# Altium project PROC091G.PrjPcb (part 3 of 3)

## Sheet PROC091G_CAN_INTERFACE.SchDoc: BREAKAWAY_SECTION5
size 431 x 279 mm; Date: Not shown in title block; ApprovedBy: Not shown in title block; CheckedBy: Not shown in title block; Author: Not shown in title block; CompanyName: Not shown in title block; DrawnBy: Antony/Bala; Engineer: Not shown in title block; Organization: Not shown in title block; Address1: Not shown in title block; Address2: Not shown in title block; Address3: Not shown in title block; Address4: Not shown in title block; DocumentNumber: 11; Revision: Use project parameter SCH_Rev; SheetNumber: 11; SheetTotal: 12; PageSetup: Record=PageOptions¦CenterHorizontal=True¦CenterVertical=True¦PrintScale=1.00¦XCorrection=1.00¦YCorrection=1.00¦PrintKind=0¦BorderSize=5000000¦LeftOffset=0¦BottomOffset=0¦Orientation=2¦PaperLength=1000¦PaperWidth=1000¦Scale=100¦PaperSource=15¦PrintQuality=600¦MediaType=1¦DitherType=10¦PaperKind=Letter¦PrintScaleMode=1
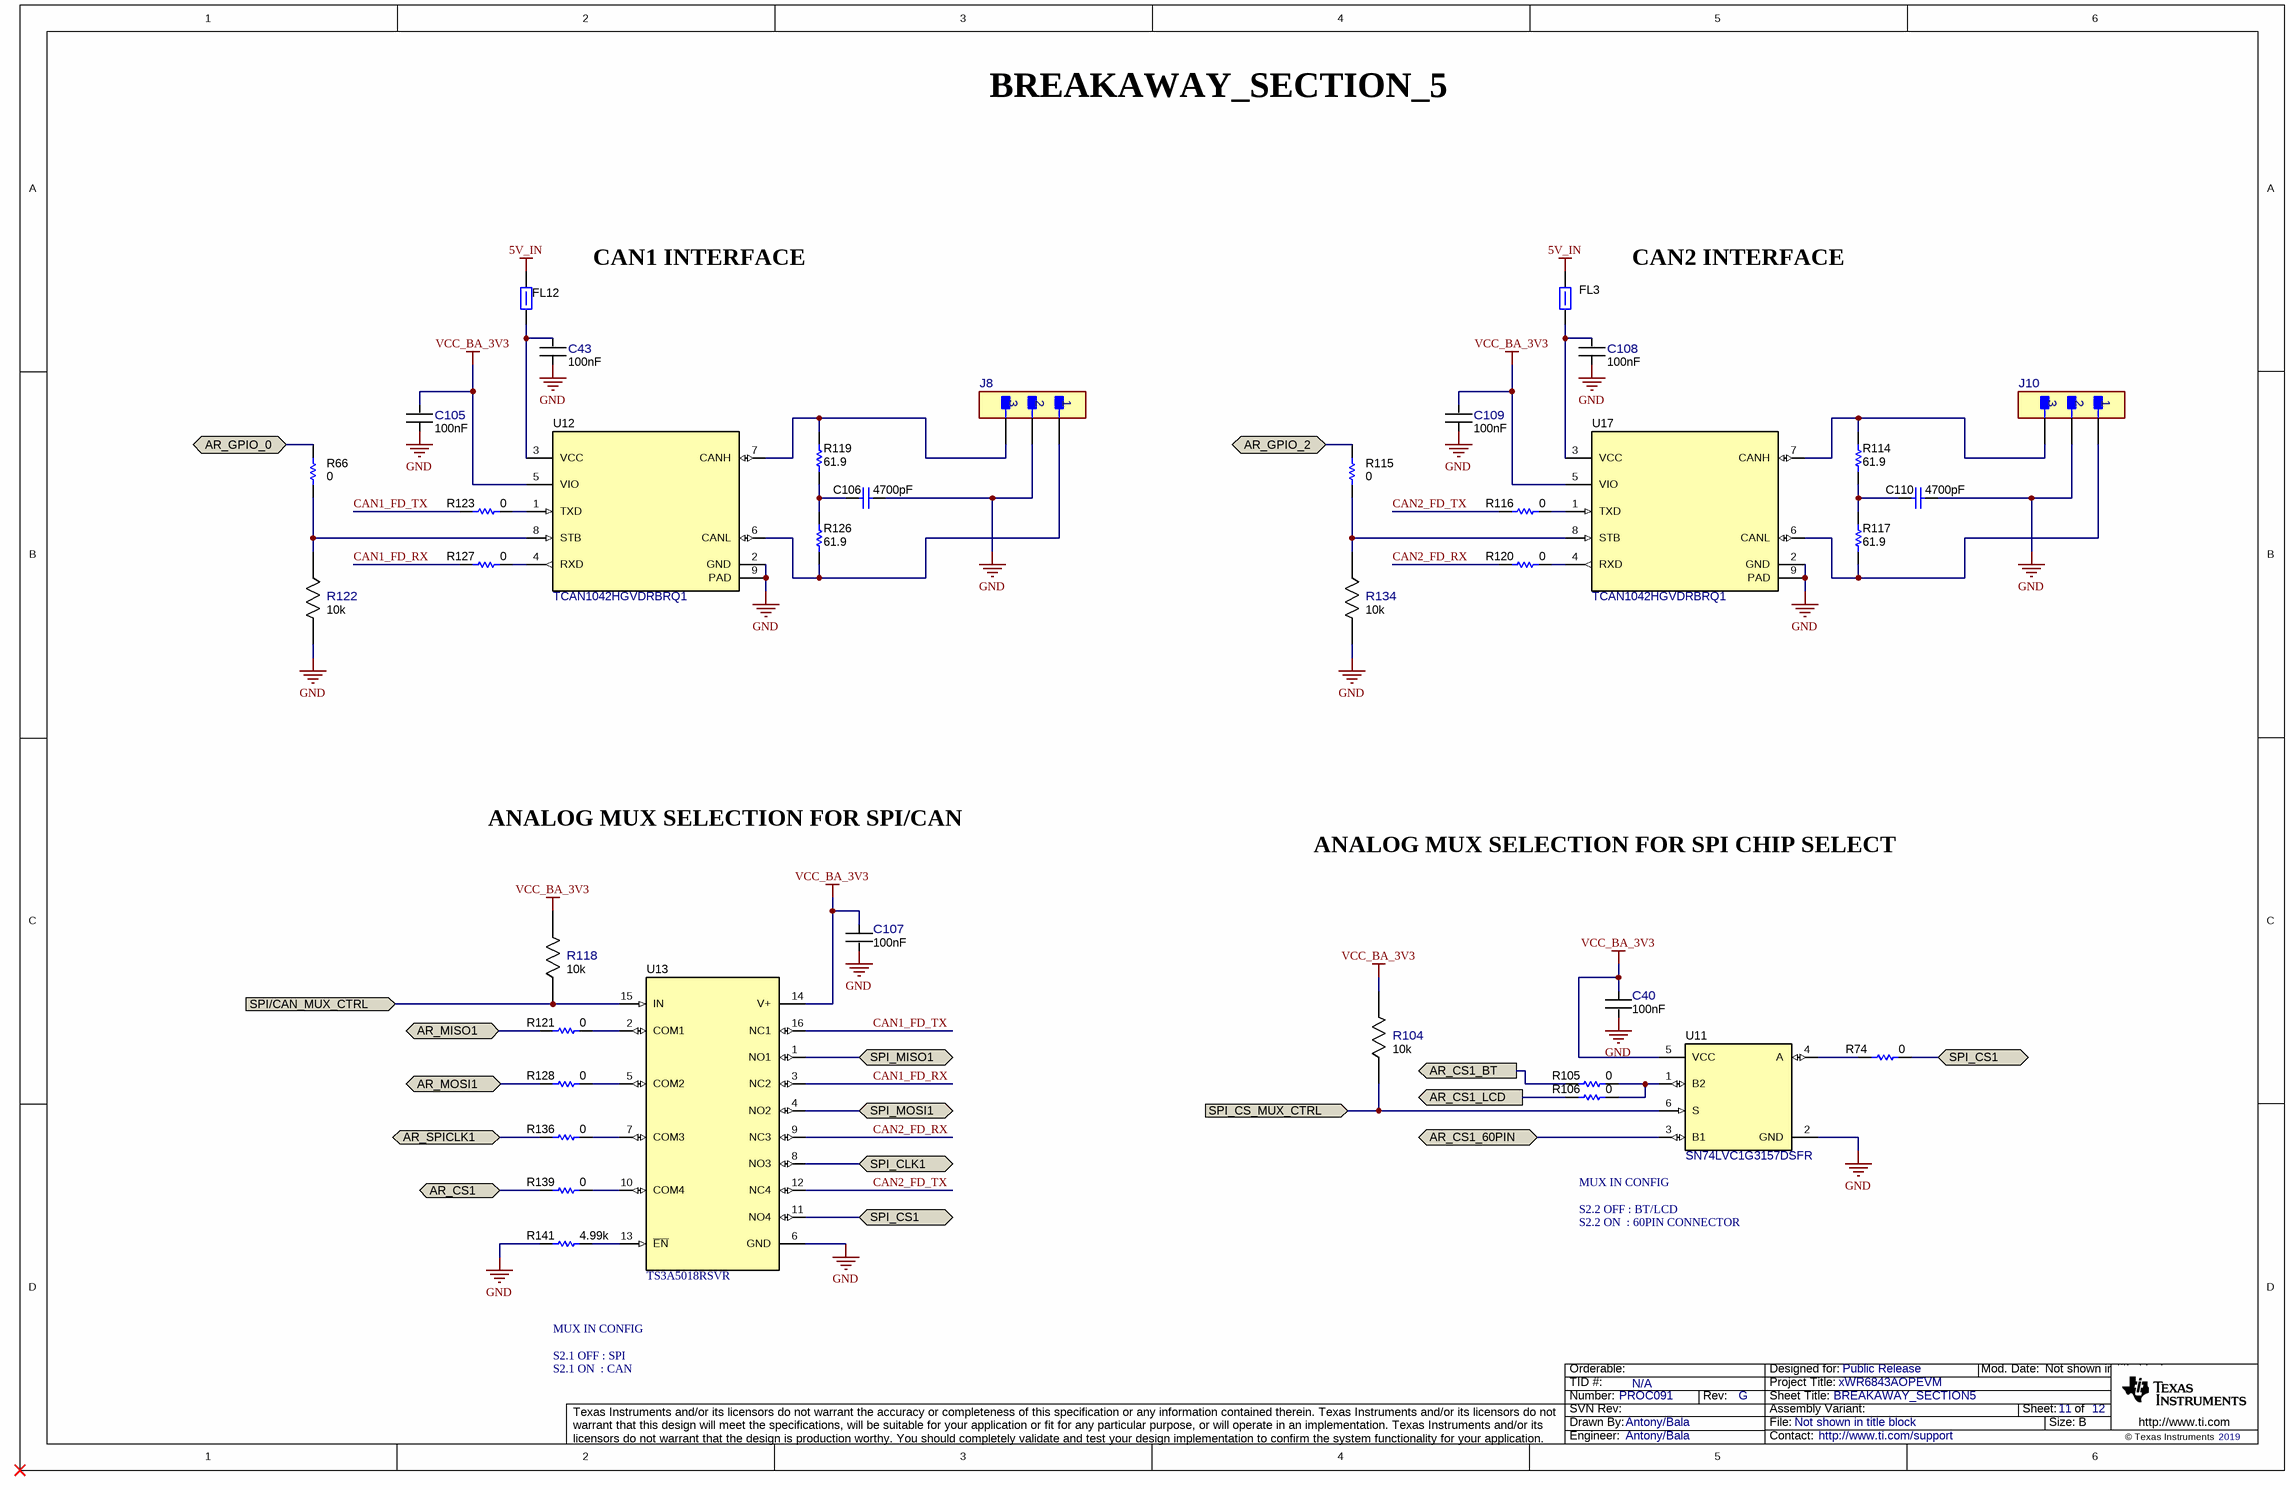
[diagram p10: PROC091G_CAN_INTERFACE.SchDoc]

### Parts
C40  Cap_F: 100nF  [FP-GRM033R6YA104KE14D_0201 (0603 Metric)-IPC_C]  (hidden comment: GRM033R6YA104KE14D)
C43  Cap_F: 100nF  [FP-GRM033R6YA104KE14D_0201 (0603 Metric)-IPC_C]  (hidden comment: GRM033R6YA104KE14D)
C105  Cap_F: 100nF  [FP-GRM033R6YA104KE14D_0201 (0603 Metric)-IPC_C]  (hidden comment: GRM033R6YA104KE14D)
C106  ValueDisplayed: 4700pF  [0402L]  (hidden comment: GRM155R71H472KA01D)
C107  Cap_F: 100nF  [FP-GRM033R6YA104KE14D_0201 (0603 Metric)-IPC_C]  (hidden comment: GRM033R6YA104KE14D)
C108  Cap_F: 100nF  [FP-GRM033R6YA104KE14D_0201 (0603 Metric)-IPC_C]  (hidden comment: GRM033R6YA104KE14D)
C109  Cap_F: 100nF  [FP-GRM033R6YA104KE14D_0201 (0603 Metric)-IPC_C]  (hidden comment: GRM033R6YA104KE14D)
C110  ValueDisplayed: 4700pF  [0402L]  (hidden comment: GRM155R71H472KA01D)
FL3  BLM15PD300SZ1D  [0402L]  (value not drawn)
FL12  BLM15PD300SZ1D  [0402L]  (value not drawn)
J8  M50-3930342  [FP-M50-3930342_HDR3-MFG]  (value not drawn)
J10  M50-3930342  [FP-M50-3930342_HDR3-MFG]  (value not drawn)
R66  Res_ohm: 0  [FP-RC0201JR-070RL_0201 (0603 Metric)-IPC_C]  (hidden comment: RC0201JR-070RL)
R74  Res_ohm: 0  [FP-RC0201JR-070RL_0201 (0603 Metric)-IPC_C]  (hidden comment: RC0201JR-070RL)
R104  Res_ohm: 10k  [FP-RR0306P-103-D_0201-IPC_C]  (hidden comment: RR0306P-103-D)
R105  Res_ohm: 0  [FP-RC0201JR-070RL_0201 (0603 Metric)-IPC_C]  (hidden comment: RC0201JR-070RL)
R106  Res_ohm: 0  [FP-RC0201JR-070RL_0201 (0603 Metric)-IPC_C]  (hidden comment: RC0201JR-070RL)
R114  ValueDisplayed: 61.9  [0402L]  (hidden comment: CRCW040261R9FKED)
R115  Res_ohm: 0  [FP-RC0201JR-070RL_0201 (0603 Metric)-IPC_C]  (hidden comment: RC0201JR-070RL)
R116  Res_ohm: 0  [FP-RC0201JR-070RL_0201 (0603 Metric)-IPC_C]  (hidden comment: RC0201JR-070RL)
R117  ValueDisplayed: 61.9  [0402L]  (hidden comment: CRCW040261R9FKED)
R118  Res_ohm: 10k  [FP-RR0306P-103-D_0201-IPC_C]  (hidden comment: RR0306P-103-D)
R119  ValueDisplayed: 61.9  [0402L]  (hidden comment: CRCW040261R9FKED)
R120  Res_ohm: 0  [FP-RC0201JR-070RL_0201 (0603 Metric)-IPC_C]  (hidden comment: RC0201JR-070RL)
R121  Res_ohm: 0  [FP-RC0201JR-070RL_0201 (0603 Metric)-IPC_C]  (hidden comment: RC0201JR-070RL)
R122  Res_ohm: 10k  [FP-RR0306P-103-D_0201-IPC_C]  (hidden comment: RR0306P-103-D)
R123  Res_ohm: 0  [FP-RC0201JR-070RL_0201 (0603 Metric)-IPC_C]  (hidden comment: RC0201JR-070RL)
R126  ValueDisplayed: 61.9  [0402L]  (hidden comment: CRCW040261R9FKED)
R127  Res_ohm: 0  [FP-RC0201JR-070RL_0201 (0603 Metric)-IPC_C]  (hidden comment: RC0201JR-070RL)
R128  Res_ohm: 0  [FP-RC0201JR-070RL_0201 (0603 Metric)-IPC_C]  (hidden comment: RC0201JR-070RL)
R134  Res_ohm: 10k  [FP-RR0306P-103-D_0201-IPC_C]  (hidden comment: RR0306P-103-D)
R136  Res_ohm: 0  [FP-RC0201JR-070RL_0201 (0603 Metric)-IPC_C]  (hidden comment: RC0201JR-070RL)
R139  Res_ohm: 0  [FP-RC0201JR-070RL_0201 (0603 Metric)-IPC_C]  (hidden comment: RC0201JR-070RL)
R141  value 4.99k  [0201L]  (hidden comment: RC0201FR-074K99L)
U11  SN74LVC1G3157DSFR  [DSF0006A]
U12  TCAN1042HGVDRBRQ1  [DRB0008F]
U13  TS3A5018RSVR  [RSV0016A]
U17  TCAN1042HGVDRBRQ1  [DRB0008F]

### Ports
AR_CS1 (bidir), AR_CS1_60PIN (bidir), AR_CS1_BT (out), AR_CS1_LCD (out), AR_GPIO_0 (bidir), AR_GPIO_2 (bidir), AR_MISO1 (bidir), AR_MOSI1 (bidir), AR_SPICLK1 (bidir), SPI/CAN_MUX_CTRL (in), SPI_CLK1 (bidir), SPI_CS1 (bidir), SPI_CS_MUX_CTRL (in), SPI_MISO1 (bidir), SPI_MOSI1 (bidir)

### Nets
5V_IN: FL3.2 FL12.2
GND: C40.2 C43.1 C105.1 C106.1 C107.2 C108.1 C109.1 C110.1 J8.2 J10.2 R122.2 R134.2 R141.2 U11.2(GND) U12.2(GND) U12.9(PAD) U13.6(GND) U17.2(GND) U17.9(PAD)
VCC_BA_3V3: C40.1 C105.2 C107.1 C109.2 R104.2 R118.2 U11.5(VCC) U12.5(VIO) U13.14(V+) U17.5(VIO)
AR_CS1: R139.2 ; port AR_CS1
AR_CS1_60PIN: U11.3(B1) ; port AR_CS1_60PIN
AR_CS1_BT: R105.2 ; port AR_CS1_BT
AR_CS1_LCD: R106.2 ; port AR_CS1_LCD
AR_GPIO_0: R66.1 ; port AR_GPIO_0
AR_GPIO_2: R115.1 ; port AR_GPIO_2
AR_MISO1: R121.2 ; port AR_MISO1
AR_MOSI1: R128.2 ; port AR_MOSI1
AR_SPICLK1: R136.2 ; port AR_SPICLK1
CAN1_FD_RX: R127.2 U13.3(NC2)
CAN1_FD_TX: R123.2 U13.16(NC1)
CAN2_FD_RX: R120.2 U13.9(NC3)
CAN2_FD_TX: R116.2 U13.12(NC4)
SPI/CAN_MUX_CTRL: R118.1 U13.15(IN) ; port SPI/CAN_MUX_CTRL
SPI_CLK1: U13.8(NO3) ; port SPI_CLK1
SPI_CS1: R74.1 U13.11(NO4) ; port SPI_CS1
SPI_CS_MUX_CTRL: R104.1 U11.6(S) ; port SPI_CS_MUX_CTRL
SPI_MISO1: U13.1(NO1) ; port SPI_MISO1
SPI_MOSI1: U13.4(NO2) ; port SPI_MOSI1
NetC43_2: C43.2 FL12.1 U12.3(VCC)
NetC106_2: C106.2 R119.1 R126.2
NetC108_2: C108.2 FL3.1 U17.3(VCC)
NetC110_2: C110.2 R114.1 R117.2
NetJ8_1: J8.1 R126.1 U12.6(CANL)
NetJ8_3: J8.3 R119.2 U12.7(CANH)
NetJ10_1: J10.1 R117.1 U17.6(CANL)
NetJ10_3: J10.3 R114.2 U17.7(CANH)
NetR66_2: R66.2 R122.1 U12.8(STB)
NetR74_2: R74.2 U11.4(A)
NetR105_1: R105.1 R106.1 U11.1(B2)
NetR115_2: R115.2 R134.1 U17.8(STB)
NetR116_1: R116.1 U17.1(TXD)
NetR120_1: R120.1 U17.4(RXD)
NetR121_1: R121.1 U13.2(COM1)
NetR123_1: R123.1 U12.1(TXD)
NetR127_1: R127.1 U12.4(RXD)
NetR128_1: R128.1 U13.5(COM2)
NetR136_1: R136.1 U13.7(COM3)
NetR139_1: R139.1 U13.10(COM4)
NetR141_1: R141.1 U13.13(~{EN})

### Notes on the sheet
- BREAKAWAY_SECTION_5
- CAN1 INTERFACE
- CAN2 INTERFACE
- ANALOG MUX SELECTION FOR SPI/CAN
- ANALOG MUX SELECTION FOR SPI CHIP SELECT
- (near U11) MUX IN CONFIG
- S2.2 ON  : 60PIN CONNECTOR
- S2.2 OFF : BT/LCD
- MUX IN CONFIG
- S2.1 OFF : SPI
- S2.1 ON  : CAN

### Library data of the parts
C40 C43 C105 C107-C109 = CMP-0086440-1: Cap Ceramic 0.1uF 35V X5R 10% Pad SMD 0201 85C T/R; Manufacturer: Murata Electronics North America; AEC Qualified: No; SizeZ_mm: 0.33mm; Symbol Name: SYM-GRM033R6YA104KE14D; TempCo: 15%
C106 C110 = CMP-0006692-2: CAP, CERM, 4700 pF, 50 V, +/- 10%, X7R, 0402; Manufacturer: MuRata; TaMin_C: -55°C; Polarized: N; SizeAreaWB_mm2: 3; Value1: Unknown; U/M: EA; Value: 4700pF; TaMax_C: 125°C; SizeZ_mm: 0.6; SizeX_mm: 1; SizeY_mm: 0.5; Cap_Case: 0402; Value2: 50V; Cap_F: 4.7nF; AEC Category: Q200
FL3 FL12 = CMP-0078934-1: Inductor, Ferrite Bead, Ferrite, 2.2 A, 0.035 ohm, AEC-Q200 Grade 1, SMD; Manufacturer: MuRata; AEC Category: Q200; AEC Grade: 1; AEC Qualified: Y; DCR_ohm: 0.035; Imax_A: 2.2A; SizeArea_mm2: 0.5; SizeAreaWB_mm2: 3; SizeZ_mm: 0.6
J8 J10 = CMP-0087785-1: CONN HEADER R/A 3POS 1.27MM; Manufacturer: Harwin; Row_Count: 1; Current_A: 1A; ContactFinish: Gold,Nickel
R66 R74 R105 R106 R115 R116 R120 R121 R123 R127 R128 R136 R139 = CMP-0086442-2: RES SMD 0 OHM JUMPER 1/20W 0201; Manufacturer: Yageo; AEC Qualified: No; Power_W: 50mW; SizeZ_mm: 0.26mm; TempCo: 200ppm/°C; Tolerance_%: 5%; VDC_V: 25V
R104 R118 R122 R134 = CMP-0088002-1: 10 kOhms ±0.5% 0.05W, 1/20W Chip Resistor 0201 (0603 Metric)  Thin Film; Manufacturer: Susumu; AEC Qualified: No; Power_W: 50mW; SizeZ_mm: 0.26mm; Symbol Name: SYM-RR0306P-103-D; TempCo: 25ppm/°C; VDC_V: 15V
R114 R117 R119 R126 = CMP-0026491-2: RES, 61.9, 1%, 0.063 W, AEC-Q200 Grade 0, 0402; Manufacturer: Vishay-Dale; Power_W: 63mW; TempCo: 100 ppm/C; Value_Code: 61R9; Value: 61.9; EIA_Code: E96; SizeX_mm: 1; SizeY_mm: 0.5; SizeZ_mm: 0.6; Value2: 0.063W; AEC Qualified: Y; VDC_V: 50V; AEC Category: Q200; AEC Grade: 0
R141 = CMP-0027745-1: RES, 4.99 k, 1%, 0.05 W, 0201; Manufacturer: Yageo America; AEC Category: Q200; AEC Qualified: N; EIA_Code: E96; Power_W: 50mW; SizeArea_mm2: 0.18; SizeX_mm: 0.6; SizeY_mm: 0.3; SizeZ_mm: 0.26; TempCo: 200 ppm/C; U/M: EA; Value2: 0.05W; Value_Code: 4k99; VDC_V: 25V
U11 = CMP-0050992-5: 1-Channel, 2:1 Analog Switch, DSF0006A (X2SON-6); Manufacturer: Texas Instruments; 3-State Output: No; AEC Category: Q200; AEC Qualified: N; Bits(#): 1; CompType: IC; F @ Nom Voltage(Max)(Mhz): 150; ICC @ Nom Voltage(Max)(mA): 0.01; Input Type: CMOS/TTL; Logic: True; Mux Configuration: 1：2; Output Drive (IOL/IOH)(Max)(mA): 32/-32; Output Type: CMOS; Rating: Catalog; Switch Configuration: SPDT; Technology Family: LVC; tpd @ Nom Voltage(Max)(ns): 2,1.2,0.8,0.3; VCC(Max)(V): 5.5; VCC(Min)(V): 1.65; Voltage(Nom)(V): 1.8,2.5,3.3,5
U12 U17 = CMP-0065183-3: Automotive Fault Protected CAN Transceiver With Flexible Data-Rate, DRB0008F (VSON-8); Manufacturer: Texas Instruments; Alternate PartNumber: TCAN1042HGVDRBTQ1; SizeX_mm: 3.0; CompType: IC; SizeZ_mm: 1.0; SizeArea_mm2: 9.0; SizeAreaWB_mm2: 16.0; AEC Category: Q200; AEC Qualified: Y
U13 = CMP-0067415-1: 10-Ohm Quad SPDT Analog Switch, RSV0016A (UQFN-16); Alternate Manufacturer: Texas Instruments; SizeAreaWB_mm2: 10.08; U/M: EA; SizeZ_mm: 0.55; SizeX_mm: 1.8; SizeY_mm: 2.6; SizeArea_mm2: 4.68; CompType: IC

## Sheet PROC091G_Hardware.schdoc: HARDWARE
size 431 x 279 mm; Date: Not shown in title block; ApprovedBy: Not shown in title block; CheckedBy: Not shown in title block; Author: Not shown in title block; CompanyName: Not shown in title block; DrawnBy: Antony/Bala; Engineer: Not shown in title block; Organization: Not shown in title block; Address1: Not shown in title block; Address2: Not shown in title block; Address3: Not shown in title block; Address4: Not shown in title block; DocumentNumber: 12; Revision: Use project parameter SCH_Rev; SheetNumber: 12; SheetTotal: 12; PageSetup: Record=PageOptions¦CenterHorizontal=True¦CenterVertical=True¦PrintScale=1.00¦XCorrection=1.00¦YCorrection=1.00¦PrintKind=0¦BorderSize=5000000¦LeftOffset=0¦BottomOffset=0¦Orientation=2¦PaperLength=1000¦PaperWidth=1000¦Scale=100¦PaperSource=15¦PrintQuality=600¦MediaType=1¦DitherType=10¦PaperKind=Letter¦PrintScaleMode=1
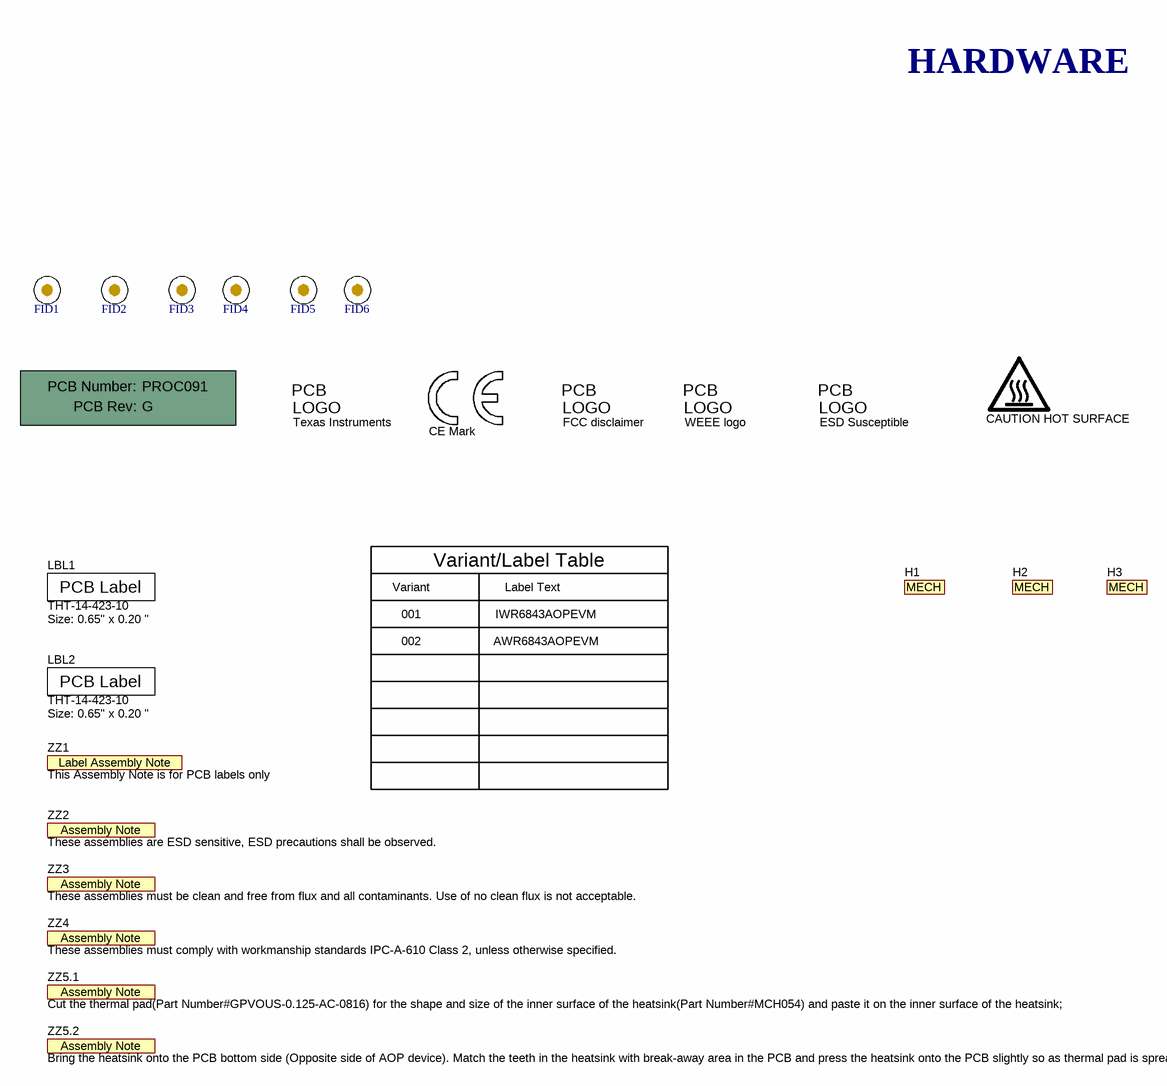
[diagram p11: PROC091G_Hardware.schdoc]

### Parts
!PCB  Printed Circuit Board  (value not drawn)  (mechanical)
CAUTION_HOT_SURFACE1  CAUTION HOT SURFACE  [IEC_HotSurface_Small]  (graphical)
ESD_Susceptible1  ESD Susceptible  [ESD_Overlay_Small]  (graphical)
FID1  Fiducial  [Fiducial6.4-20]  (value not drawn)
FID2  Fiducial  [Fiducial6.4-20]  (value not drawn)
FID3  Fiducial  [Fiducial6.4-20]  (value not drawn)
FID4  Fiducial  [Fiducial6.4-20]  (value not drawn)
FID5  Fiducial  [Fiducial6.4-20]  (value not drawn)
FID6  Fiducial  [Fiducial6.4-20]  (value not drawn)
H1  MechPart  (value not drawn)  (mechanical)
H2  MechPart  (value not drawn)  (mechanical)
H3  MechPart  (value not drawn)  (mechanical)
LBL1  THT-14-423-10  Note: Size: 0.65" x 0.20 "  [Label_650x200]  (graphical)
LBL2  THT-14-423-10  Note: Size: 0.65" x 0.20 "  [Label_650x200]  (graphical)
Logo1  Texas Instruments  [TI_Stacked_Overlay_Small]  (graphical)
Logo2  CE Mark  [CE_Mark_5mm]  (graphical)
Logo3  FCC disclaimer  [FCC_disclaimer]  (graphical)
Logo4  WEEE logo  [WEEE_Minimum]  (graphical)
ZZ1  This Assembly Note is for PCB labels only  [AssemblyNoteLabel]  (no BOM)
ZZ2  These assemblies are ESD sensitive, ESD precautions shall be observed.  [AssemblyNote]  (no BOM)
ZZ3  These assemblies must be clean and free from flux and all contaminants. Use of no clean flux is not acceptable.  [AssemblyNote]  (no BOM)
ZZ4  These assemblies must comply with workmanship standards IPC-A-610 Class 2, unless otherwise specified.  [AssemblyNote]  (no BOM)
ZZ5.1  Cut the thermal pad(Part Number#GPVOUS-0.125-AC-0816) for the shape and size of the inner surface of the heatsink(Part Number#MCH054) and paste it on the inner surface of the heatsink;  [AssemblyNote]  (no BOM)
ZZ5.2  Bring the heatsink onto the PCB bottom side (Opposite side of AOP device). Match the teeth in the heatsink with break-away area in the PCB and press the heatsink onto the PCB slightly so as thermal pad is spread all over the area  [AssemblyNote]  (no BOM)

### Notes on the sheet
- HARDWARE
- Variant/Label Table
- Variant
- 001
- 002
- Label Text
- IWR6843AOPEVM
- AWR6843AOPEVM

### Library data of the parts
!PCB = CMP-0003618-2: Manufacturer: Any; PartNumber: PROC091
CAUTION_HOT_SURFACE1 = CMP-0074837-1: IEC 61010-1 Hot Surface Warning; Library Reference: IEC_HotSurface; SymbolCreator: a0412235
ESD_Susceptible1 = CMP-0074840-1: ESD Susceptible Symbol; Library Reference: Logo; SymbolCreator: a0412235; Lib Reference: ESD_Susceptible
FID1-FID6 = CMP-0077181-1: Fiducial mark.  There is nothing to buy or mount.
H1 = CMP-0080604-2: AOP EVM Heatsink; Manufacturer: Any; PartNumber: MCH054; Alternate PartNumber: 160018120021; CompType: Mechanical
H2 = CMP-0080604-2: Thermal Pad Pink 406.40mm x 203.20mm Rectangular Adhesive - One Side; Manufacturer: Bergquist; PartNumber: GPVOUS-0.125-AC-0816; CompType: Mechanical
H3 = CMP-0080604-2: xWR6843AOPEVM Mounting stand; Manufacturer: Any; PartNumber: MCH066; Alternate PartNumber: 160021010001; CompType: Mechanical
LBL1 LBL2 = CMP-0003625-1: Thermal Transfer Printable Labels, 0.650" W x 0.200" H - 10,000 per roll; Manufacturer: Brady; CompType: Label
Logo1 = CMP-0074838-1: Texas Instrument Corporate Signature; SymbolCreator: a0412235; Lib Reference: TI_Logo; Library Reference: Logo
Logo2 = CMP-0074844-1: SymbolCreator: a0412235
Logo3 = CMP-0074847-1: FCC_disclaimer; Library Reference: Logo
Logo4 = CMP-0074769-1
ZZ1 = CMP-0003616-3
ZZ2 = CMP-0077236-1
ZZ3 = CMP-0077237-1
ZZ4 ZZ5.2 = CMP-0077238-1
ZZ5.1 = CMP-0077238-1: Cut the thermal pad(Part Number#GPVOUS-0.125-AC-0816) for the shape and size of the inner surface of the heatsink(Part Number#160018120021) and paste it on the inner surface of the heatsink;

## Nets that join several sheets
5V_IN: PROC091G_PMIC (12 pins), PROC091G_FLASH_USB_TO_UART (C1.2 C4.1 D1.1 R64.1), PROC091G_HD_CONN_PWR_SW (D2.1), PROC091G_RST_GPIOs_I2C (R107.1), PROC091G_CAN_INTERFACE (FL3.2 FL12.2)
5V_IN_B: PROC091G_HD_CONN_PWR_SW (C127.1 U19.6), PROC091G_ANALOG_MUX (C42.2 C122.1 FL14.2 TP4.1)
AR_1P0_RF1: PROC091G_AOP_PWR (7 pins), PROC091G_PMIC (C124.1 C137.1 C139.1 L12.2)
AR_1P0_RF2: PROC091G_AOP_PWR (15 pins), PROC091G_PMIC (5 pins)
AR_1P2: PROC091G_AOP_PWR (19 pins), PROC091G_PMIC (C133.1 C134.1 C141.1 L13.2)
AR_1V8: PROC091G_AOP_PWR (26 pins), PROC091G_PMIC (C135.1 C136.1 C138.1 L11.2)
AR_VBGAP: PROC091G_AOP_IO (U2.A16), PROC091G_AOP_PWR (C69.1)
GND: PROC091G_AOP_IO (11 pins), PROC091G_AOP_PWR (116 pins), PROC091G_PMIC (38 pins), PROC091G_FLASH_USB_TO_UART (21 pins), PROC091G_HD_CONN_PWR_SW (30 pins), PROC091G_RST_GPIOs_I2C (30 pins), PROC091G_BT_DISPLAY (50 pins), PROC091G_ANALOG_MUX (17 pins), PROC091G_CAN_INTERFACE (19 pins)
PMIC_3V3: PROC091G_AOP_IO (12 pins), PROC091G_AOP_PWR (5 pins), PROC091G_PMIC (5 pins), PROC091G_FLASH_USB_TO_UART (15 pins), PROC091G_HD_CONN_PWR_SW (FL22.1)
VCC_BA_3V3: PROC091G_HD_CONN_PWR_SW (FL22.2 TP13.1), PROC091G_RST_GPIOs_I2C (26 pins), PROC091G_BT_DISPLAY (13 pins), PROC091G_ANALOG_MUX (C123.1 R1.2 R16.1 U15.8), PROC091G_CAN_INTERFACE (10 pins)
ALERT: PROC091G_RST_GPIOs_I2C (R38.1 U5.3), PROC091G_BT_DISPLAY (U10.4)
AR_BSS_LOGGER: PROC091G_AOP_IO (U2.D3), PROC091G_HD_CONN_PWR_SW (RA2.2)
AR_CS1: PROC091G_AOP_IO (R9.2 U2.C2), PROC091G_CAN_INTERFACE (R139.2)
AR_CS1_60PIN: PROC091G_HD_CONN_PWR_SW (R150.2 RA3.1), PROC091G_CAN_INTERFACE (U11.3)
AR_CS1_BT: PROC091G_BT_DISPLAY (U8.30), PROC091G_CAN_INTERFACE (R105.2)
AR_CS1_LCD: PROC091G_BT_DISPLAY (R76.2), PROC091G_CAN_INTERFACE (R106.2)
AR_DMM_CLK: PROC091G_AOP_IO (U2.U3), PROC091G_HD_CONN_PWR_SW (J11.15 R11.1)
AR_DMM_SYNC: PROC091G_AOP_IO (U2.U4), PROC091G_HD_CONN_PWR_SW (J11.17 R10.1)
AR_DP0: PROC091G_AOP_IO (U2.U7), PROC091G_HD_CONN_PWR_SW (J11.19 R88.1)
AR_DP1: PROC091G_AOP_IO (U2.U6), PROC091G_HD_CONN_PWR_SW (J11.21 R130.1)
AR_DP2: PROC091G_AOP_IO (U2.V5), PROC091G_HD_CONN_PWR_SW (J11.23 R132.1)
AR_DP3: PROC091G_AOP_IO (U2.U5), PROC091G_HD_CONN_PWR_SW (J11.25 R133.1)
AR_DP4: PROC091G_AOP_IO (U2.V3), PROC091G_HD_CONN_PWR_SW (J11.27 R135.1)
AR_DP5: PROC091G_AOP_IO (U2.M1), PROC091G_HD_CONN_PWR_SW (J11.29 R137.1)
AR_DP6: PROC091G_AOP_IO (U2.L2), PROC091G_HD_CONN_PWR_SW (J11.31 R138.1)
AR_DP7: PROC091G_AOP_IO (U2.L1), PROC091G_HD_CONN_PWR_SW (J11.33 R140.1)
AR_GPIO_0: PROC091G_AOP_IO (U2.M2), PROC091G_HD_CONN_PWR_SW (RA5.8), PROC091G_CAN_INTERFACE (R66.1)
AR_GPIO_1: PROC091G_AOP_IO (U2.L3), PROC091G_HD_CONN_PWR_SW (RA5.7), PROC091G_RST_GPIOs_I2C (R129.2)
AR_GPIO_2: PROC091G_AOP_IO (U2.K3), PROC091G_HD_CONN_PWR_SW (RA5.6), PROC091G_RST_GPIOs_I2C (LD3.1), PROC091G_CAN_INTERFACE (R115.1)
AR_HOSTINTR1: PROC091G_AOP_IO (R3.1 U2.B2), PROC091G_HD_CONN_PWR_SW (R152.1 RA9.6)
AR_LVDS_0_N: PROC091G_AOP_IO (U2.N1), PROC091G_HD_CONN_PWR_SW (R149.1 RA6.7)
AR_LVDS_0_P: PROC091G_AOP_IO (U2.N2), PROC091G_HD_CONN_PWR_SW (R148.1 RA6.8)
AR_LVDS_1_N: PROC091G_AOP_IO (U2.P1), PROC091G_HD_CONN_PWR_SW (R147.1 RA7.5)
AR_LVDS_1_P: PROC091G_AOP_IO (U2.P2), PROC091G_HD_CONN_PWR_SW (R146.1 RA7.6)
AR_LVDS_CLK_N: PROC091G_AOP_IO (U2.R2), PROC091G_HD_CONN_PWR_SW (R145.1 RA7.7)
AR_LVDS_CLK_P: PROC091G_AOP_IO (U2.R1), PROC091G_HD_CONN_PWR_SW (R144.1 RA7.8)
AR_LVDS_FRCLK_N: PROC091G_AOP_IO (U2.T2), PROC091G_HD_CONN_PWR_SW (R143.1 RA8.5)
AR_LVDS_FRCLK_P: PROC091G_AOP_IO (U2.T1), PROC091G_HD_CONN_PWR_SW (R142.1 RA8.6)
AR_MCUCLKOUT: PROC091G_AOP_IO (U2.V13), PROC091G_HD_CONN_PWR_SW (RA1.1)
AR_MISO1: PROC091G_AOP_IO (U2.D1), PROC091G_CAN_INTERFACE (R121.2)
AR_MOSI1: PROC091G_AOP_IO (U2.F2), PROC091G_CAN_INTERFACE (R128.2)
AR_MSS_LOGGER: PROC091G_AOP_IO (U2.E2), PROC091G_FLASH_USB_TO_UART (U3.20), PROC091G_HD_CONN_PWR_SW (R58.1), PROC091G_BT_DISPLAY (R131.1)
AR_NERR_OUT: PROC091G_AOP_IO (R21.1 U2.U15), PROC091G_HD_CONN_PWR_SW (RA6.5)
AR_NERRIN: PROC091G_AOP_IO (R22.1 U2.U14), PROC091G_HD_CONN_PWR_SW (RA6.6)
AR_NRST: PROC091G_AOP_IO (C130.1 R59.1 TP14.1 U2.U11), PROC091G_RST_GPIOs_I2C (R108.1 U16.4)
AR_NRST_1: PROC091G_HD_CONN_PWR_SW (R190.2 RA9.8), PROC091G_RST_GPIOs_I2C (R177.2 U16.1)
AR_OSC_CLKOUT: PROC091G_AOP_IO (TP17.1 U2.A14), PROC091G_HD_CONN_PWR_SW (RA1.2)
AR_PMIC_CLKOUT_SOP2: PROC091G_AOP_IO (R85.1 R103.1 U2.V10), PROC091G_HD_CONN_PWR_SW (RA1.4)
AR_QSPI_CLK: PROC091G_AOP_IO (U2.H2), PROC091G_FLASH_USB_TO_UART (R47.1)
AR_QSPI_CS: PROC091G_AOP_IO (U2.J2), PROC091G_FLASH_USB_TO_UART (R43.1 U9.1)
AR_QSPI_D0: PROC091G_AOP_IO (U2.H3), PROC091G_FLASH_USB_TO_UART (R6.1)
AR_QSPI_D1: PROC091G_AOP_IO (U2.G2), PROC091G_FLASH_USB_TO_UART (R46.1)
AR_QSPI_D2: PROC091G_AOP_IO (U2.J3), PROC091G_FLASH_USB_TO_UART (R44.1 R48.1)
AR_QSPI_D3: PROC091G_AOP_IO (U2.K2), PROC091G_FLASH_USB_TO_UART (R45.1 R49.1)
AR_RS232RX: PROC091G_AOP_IO (R5.2 U2.V16), PROC091G_FLASH_USB_TO_UART (U18.6)
AR_RS232RX_BT: PROC091G_BT_DISPLAY (R102.1), PROC091G_ANALOG_MUX (U15.4)
AR_RS232TX: PROC091G_AOP_IO (R4.2 U2.U16), PROC091G_FLASH_USB_TO_UART (U18.10)
AR_RS232TX_BT: PROC091G_BT_DISPLAY (R90.1), PROC091G_ANALOG_MUX (U15.2)
AR_SCL: PROC091G_AOP_IO (R8.1 R62.2), PROC091G_PMIC (R32.1), PROC091G_HD_CONN_PWR_SW (R187.2 RA2.4), PROC091G_RST_GPIOs_I2C (J3.2 R51.1 R67.1 R70.2), PROC091G_BT_DISPLAY (R99.2)
AR_SDA: PROC091G_AOP_IO (R7.1 R61.2), PROC091G_PMIC (R28.1), PROC091G_HD_CONN_PWR_SW (R186.2 RA2.3), PROC091G_RST_GPIOs_I2C (J3.3 R57.1 R68.1 R71.2), PROC091G_BT_DISPLAY (R101.2)
AR_SPICLK1: PROC091G_AOP_IO (R75.2 U2.D2), PROC091G_CAN_INTERFACE (R136.2)
AR_SYNC_IN: PROC091G_AOP_IO (U2.U12), PROC091G_HD_CONN_PWR_SW (R157.1 RA8.8)
AR_SYNC_OUT_SOP1: PROC091G_AOP_IO (R84.1 U2.M3), PROC091G_HD_CONN_PWR_SW (RA8.7)
AR_TCK: PROC091G_AOP_IO (U2.T3), PROC091G_HD_CONN_PWR_SW (RA4.2)
AR_TDI: PROC091G_AOP_IO (U2.U9), PROC091G_HD_CONN_PWR_SW (RA4.4)
AR_TDO_SOP0: PROC091G_AOP_IO (R83.1 U2.U10), PROC091G_HD_CONN_PWR_SW (RA4.3)
AR_TMS: PROC091G_AOP_IO (U2.U8), PROC091G_HD_CONN_PWR_SW (RA4.1)
AR_WARMRST: PROC091G_AOP_IO (R23.1 U2.U13), PROC091G_HD_CONN_PWR_SW (RA1.3)
BREAK_RS232RX: PROC091G_FLASH_USB_TO_UART (TP19.1 U18.7), PROC091G_ANALOG_MUX (U15.6)
BREAK_RS232TX: PROC091G_FLASH_USB_TO_UART (TP18.1 U18.9), PROC091G_ANALOG_MUX (U15.10)
BT ENABLE: PROC091G_BT_DISPLAY (R30.1 R110.1 U8.17), PROC091G_ANALOG_MUX (S2.3)
CONN_AR_RS232RX: PROC091G_HD_CONN_PWR_SW (R14.2 R188.2), PROC091G_ANALOG_MUX (U15.7)
CONN_AR_RS232TX: PROC091G_HD_CONN_PWR_SW (R12.2 R189.2), PROC091G_ANALOG_MUX (U15.9)
PGOOD: PROC091G_PMIC (R31.1 R37.2), PROC091G_HD_CONN_PWR_SW (R155.2 RA9.7)
PMIC_CLK: PROC091G_AOP_IO (R103.2), PROC091G_PMIC (U1.3)
SENS_INT: PROC091G_RST_GPIOs_I2C (R18.2 U7.14), PROC091G_BT_DISPLAY (R100.1)
SENS_NRST: PROC091G_RST_GPIOs_I2C (R81.2 R97.2), PROC091G_BT_DISPLAY (U10.7)
SOP0: PROC091G_AOP_IO (R159.2), PROC091G_ANALOG_MUX (S1.3)
SOP1: PROC091G_AOP_IO (R171.2), PROC091G_ANALOG_MUX (S1.4)
SPI/CAN_MUX_CTRL: PROC091G_ANALOG_MUX (S2.1), PROC091G_CAN_INTERFACE (R118.1 U13.15)
SPI_CLK1: PROC091G_HD_CONN_PWR_SW (R151.2 RA3.2), PROC091G_BT_DISPLAY (R160.2 R161.1), PROC091G_CAN_INTERFACE (U13.8)
SPI_CS_MUX_CTRL: PROC091G_ANALOG_MUX (S2.2), PROC091G_CAN_INTERFACE (R104.1 U11.6)
SPI_MISO1: PROC091G_HD_CONN_PWR_SW (R154.1 RA3.4), PROC091G_BT_DISPLAY (R87.1 R166.2), PROC091G_CAN_INTERFACE (U13.1)
SPI_MOSI1: PROC091G_HD_CONN_PWR_SW (R153.2 RA3.3), PROC091G_BT_DISPLAY (R86.1), PROC091G_CAN_INTERFACE (U13.4)
UART_MUX_CTRL1: PROC091G_FLASH_USB_TO_UART (R19.1 U18.1 U18.5), PROC091G_ANALOG_MUX (S1.1)

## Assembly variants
001: not fitted C5 C7 C8 C9 C10 C11 C13 C15 C16 C17 C18 C38 C39 C73 C104 C114 C115 C116 C118 C119 FID1 FID2 FID3 FID4 FID5 FID6 FL4 J4 J6 L15 R10 R11 R18 R20 R30 R66 R70 R71 R72 R73 R76 R77 R78 R79 R80 R81 R82 R88 R92 R93 R96 R97 R98 R103 R106 R109 R115 R130 R132 R133 R135 R137 R138 R140 R160 R166 R168 R180 R181 R182 R183 R184 R185 R188 R189 U4 U7 U14 Y4
002: not fitted C5 C7 C8 C9 C10 C11 C13 C15 C16 C17 C18 C38 C39 C73 C104 C114 C115 C116 C118 C119 FID1 FID2 FID3 FID4 FID5 FID6 FL4 J4 J6 L15 R10 R11 R18 R20 R30 R66 R70 R71 R72 R73 R76 R77 R78 R79 R80 R81 R82 R88 R92 R93 R96 R97 R98 R103 R106 R109 R115 R130 R132 R133 R135 R137 R138 R140 R160 R166 R168 R180 R181 R182 R183 R184 R185 R188 R189 U4 U7 U14 Y4; alternate parts U2 -> CMP-0860942-3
